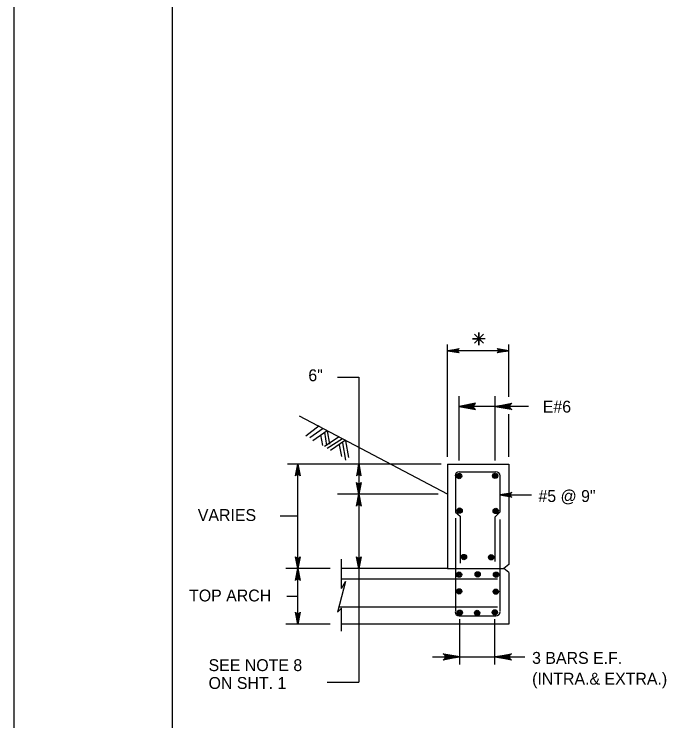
# Model space of a CAD drawing. Extents: x 639028 to 639883, y 298843 to 300031.
# Drawn here: x 639027.7 to 639195.5, y 299029.7 to 299207.9 of the extents above; entities that cross this region are included whole.
import ezdxf

# ---------------------------------------------------------------- set-up
doc = ezdxf.new("R2010")
doc.units = 0
for name, color, linetype in [('2', 7, 'Continuous'), ('52', 7, 'Continuous'), ('PLT-BNDY', 7, 'Continuous')]:
    doc.layers.add(name, color=color, linetype=linetype)

msp = doc.modelspace()

# ---------------------------------------------------------------- linework, layer by layer
at = {"layer": '2'}
for p, q in [((639067.74, 298858.08), (639067.74, 299422.08)), ((639145.06, 299126.04), (639145.06, 299126.04)), ((639137.11, 299096.29), (639137.11, 299124.56)), ((639152.61, 299111.37), (639152.61, 299124.56)), ((639152.61, 299123.03), (639137.11, 299123.03)), ((639109.36, 299116.33), (639114.74, 299116.33)), ((639114.74, 299116.33), (639114.74, 299094.45)), ((639140.04, 299095.33), (639140.04, 299111.56)), ((639149.16, 299095.33), (639149.16, 299111.56)), ((639157.6, 299108.97), (639140.04, 299108.97)), ((639137.11, 299086.83), (639099.74, 299106.53)), ((639152.61, 299096.29), (639152.61, 299107.03)), ((639104.74, 299104.08), (639101.36, 299101.45)), ((639105.74, 299103.45), (639102.36, 299101.08)), ((639106.74, 299102.83), (639103.11, 299100.33)), ((639106.11, 299102.45), (639106.61, 299099.08)), ((639106.74, 299102.83), (639107.36, 299099.45)), ((639105.11, 299101.83), (639105.61, 299099.08)), ((639109.74, 299101.33), (639106.11, 299098.83)), ((639110.61, 299100.83), (639106.74, 299098.33)), ((639111.36, 299100.45), (639107.61, 299097.83)), ((639109.74, 299099.33), (639110.36, 299096.33)), ((639110.61, 299099.83), (639111.36, 299095.45)), ((639111.36, 299100.33), (639112.11, 299096.08)), ((639135.56, 299094.45), (639096.76, 299094.45)), ((639099.36, 299068.08), (639099.36, 299094.45)), ((639114.74, 299094.45), (639114.74, 299086.83)), ((639137.11, 299094.45), (639152.61, 299094.45)), ((639137.11, 299094.45), (639137.11, 299068.08)), ((639152.61, 299094.45), (639152.61, 299069.08)), ((639140.11, 299092.45), (639149.36, 299092.45)), ((639139.11, 299091.45), (639139.11, 299082.33)), ((639150.36, 299091.45), (639150.36, 299082.33)), ((639134.74, 299086.83), (639109.36, 299086.83)), ((639114.74, 299086.83), (639114.74, 299039.39)), ((639099.36, 299081.33), (639094.86, 299081.33)), ((639139.11, 299082.33), (639140.36, 299081.33)), ((639140.36, 299081.33), (639140.36, 299069.45)), ((639150.36, 299082.33), (639149.11, 299081.08)), ((639149.11, 299081.08), (639149.11, 299069.83)), ((639139.11, 299080.83), (639139.11, 299057.33)), ((639150.36, 299080.45), (639150.36, 299057.33)), ((639110.36, 299063.08), (639110.36, 299070.45)), ((639152.61, 299069.08), (639151.36, 299068.08)), ((639107.52, 299068.08), (639096.36, 299068.08)), ((639099.36, 299054.08), (639099.36, 299068.08)), ((639137.11, 299068.08), (639110.36, 299068.08)), ((639137.11, 299068.08), (639151.36, 299068.08)), ((639152.61, 299067.08), (639151.36, 299068.08)), ((639152.61, 299067.08), (639152.61, 299054.08)), ((639149.74, 299065.45), (639110.36, 299065.45)), ((639099.36, 299061.07), (639096.56, 299061.07)), ((639149.74, 299058.33), (639109.61, 299058.33)), ((639110.36, 299052.33), (639110.36, 299058.08)), ((639149.36, 299056.08), (639140.11, 299056.08)), ((639140.22, 299043.9), (639140.22, 299055.28)), ((639149.07, 299043.9), (639149.07, 299055.28)), ((639107.52, 299054.08), (639096.36, 299054.08)), ((639152.61, 299054.08), (639110.36, 299054.08)), ((639133.31, 299045.79), (639156.66, 299045.79))]:
    msp.add_line(p, q, dxfattribs=at)
for points in [[(639146.66, 299126.04), (639143.46, 299126.04), (639145.06, 299126.04), (639145.06, 299124.44), (639145.06, 299127.64), (639145.06, 299126.04), (639146.19, 299127.17), (639143.93, 299124.91), (639145.06, 299126.04), (639146.19, 299124.91), (639143.93, 299127.17)], [(639110.36, 299063.08), (639111.36, 299064.83), (639109.36, 299057.08), (639110.36, 299058.08)], [(639140.22, 299045.79), (639136.03, 299045), (639136.19, 299045.11), (639136.35, 299045.22), (639136.43, 299045.36), (639136.52, 299045.51), (639136.54, 299045.65), (639136.56, 299045.79), (639136.54, 299045.93), (639136.52, 299046.07), (639136.43, 299046.21), (639136.35, 299046.35), (639136.19, 299046.46), (639136.03, 299046.57), (639140.22, 299045.79), (639136.19, 299046.46), (639136.35, 299046.35), (639140.22, 299045.79), (639136.43, 299046.21), (639136.52, 299046.07), (639140.22, 299045.79), (639136.54, 299045.93), (639136.56, 299045.79), (639140.22, 299045.79), (639136.54, 299045.65), (639136.52, 299045.51), (639140.22, 299045.79), (639136.43, 299045.36), (639136.35, 299045.22), (639140.22, 299045.79), (639136.19, 299045.11)], [(639149.07, 299045.79), (639153.26, 299046.57), (639153.1, 299046.46), (639152.94, 299046.35), (639152.86, 299046.21), (639152.77, 299046.07), (639152.75, 299045.93), (639152.73, 299045.79), (639152.75, 299045.65), (639152.77, 299045.51), (639152.86, 299045.36), (639152.94, 299045.22), (639153.1, 299045.11), (639153.26, 299045), (639149.07, 299045.79), (639153.1, 299045.11), (639152.94, 299045.22), (639149.07, 299045.79), (639152.86, 299045.36), (639152.77, 299045.51), (639149.07, 299045.79), (639152.75, 299045.65), (639152.73, 299045.79), (639149.07, 299045.79), (639152.75, 299045.93), (639152.77, 299046.07), (639149.07, 299045.79), (639152.86, 299046.21), (639152.94, 299046.35), (639149.07, 299045.79), (639153.1, 299046.46)]]:
    msp.add_lwpolyline(points, dxfattribs=at)
for centre, radius in [((639140.04, 299091.42), 0.668), ((639140.04, 299091.42), 0.527), ((639140.04, 299091.41), 0.37), ((639149.16, 299091.47), 0.668), ((639149.16, 299091.47), 0.527), ((639149.16, 299091.45), 0.37), ((639140.04, 299091.44), 0.202), ((639140.05, 299091.42), 0.0569), ((639149.16, 299091.48), 0.202), ((639149.18, 299091.47), 0.0569), ((639140.18, 299082.71), 0.668), ((639140.18, 299082.71), 0.527), ((639140.18, 299082.7), 0.37), ((639140.18, 299082.72), 0.202), ((639149.3, 299082.61), 0.668), ((639149.3, 299082.61), 0.527), ((639149.3, 299082.6), 0.37), ((639149.3, 299082.63), 0.202), ((639140.19, 299082.71), 0.0569), ((639149.31, 299082.61), 0.0569), ((639141.27, 299070.99), 0.668), ((639141.27, 299070.99), 0.527), ((639141.27, 299070.97), 0.37), ((639141.27, 299071), 0.202), ((639141.28, 299070.99), 0.0569), ((639148.15, 299070.94), 0.668), ((639148.15, 299070.94), 0.527), ((639148.15, 299070.93), 0.37), ((639148.15, 299070.96), 0.202), ((639148.17, 299070.94), 0.0569), ((639140.04, 299066.56), 0.668), ((639140.04, 299066.56), 0.527), ((639140.04, 299066.55), 0.37), ((639144.74, 299066.61), 0.668), ((639144.74, 299066.61), 0.527), ((639144.74, 299066.59), 0.37), ((639144.74, 299066.62), 0.202), ((639149.39, 299066.52), 0.668), ((639149.39, 299066.52), 0.527), ((639149.39, 299066.5), 0.37), ((639140.04, 299066.58), 0.202), ((639140.05, 299066.56), 0.0569), ((639144.75, 299066.61), 0.0569), ((639149.39, 299066.53), 0.202), ((639149.4, 299066.52), 0.0569), ((639140.06, 299062.33), 0.668), ((639140.06, 299062.33), 0.527), ((639140.06, 299062.32), 0.37), ((639140.06, 299062.34), 0.202), ((639140.07, 299062.33), 0.0569), ((639149.31, 299062.26), 0.668), ((639149.31, 299062.26), 0.527), ((639149.31, 299062.24), 0.37), ((639149.31, 299062.27), 0.202), ((639149.33, 299062.26), 0.0569), ((639140.22, 299056.94), 0.668), ((639140.22, 299056.94), 0.527), ((639140.22, 299056.92), 0.37), ((639140.22, 299056.95), 0.202), ((639140.24, 299056.94), 0.0569), ((639144.6, 299056.89), 0.668), ((639144.6, 299056.89), 0.527), ((639144.6, 299056.88), 0.37), ((639144.6, 299056.91), 0.202), ((639144.61, 299056.89), 0.0569), ((639149.07, 299057.03), 0.668), ((639149.07, 299057.03), 0.527), ((639149.07, 299057.02), 0.37), ((639149.07, 299057.05), 0.202), ((639149.08, 299057.03), 0.0569)]:
    msp.add_circle(centre, radius, dxfattribs=at)
for centre, start, end in [((639140.07, 299091.47), 90, 180), ((639149.35, 299091.47), 0, 90), ((639140.07, 299057.18), 180, 270), ((639149.35, 299057.18), 270, 0)]:
    msp.add_arc(centre, 1.03, start, end, dxfattribs=at)
at = {"layer": '52'}
for points in [[(639137.11, 299123.03), (639140.1, 299123.59), (639139.98, 299123.51), (639139.87, 299123.43), (639139.81, 299123.33), (639139.75, 299123.23), (639139.73, 299123.13), (639139.71, 299123.03), (639139.73, 299122.93), (639139.75, 299122.83), (639139.81, 299122.73), (639139.87, 299122.63), (639139.98, 299122.55), (639140.1, 299122.47), (639137.11, 299123.03), (639139.98, 299122.55), (639139.87, 299122.63), (639137.11, 299123.03), (639139.81, 299122.73), (639139.75, 299122.83), (639137.11, 299123.03), (639139.73, 299122.93), (639139.71, 299123.03), (639137.11, 299123.03), (639139.73, 299123.13), (639139.75, 299123.23), (639137.11, 299123.03), (639139.81, 299123.33), (639139.87, 299123.43), (639137.11, 299123.03), (639139.98, 299123.51)], [(639152.61, 299123.03), (639149.63, 299122.47), (639149.75, 299122.55), (639149.86, 299122.63), (639149.92, 299122.73), (639149.98, 299122.83), (639150, 299122.93), (639150.01, 299123.03), (639150, 299123.13), (639149.98, 299123.23), (639149.92, 299123.33), (639149.86, 299123.43), (639149.75, 299123.51), (639149.63, 299123.59), (639152.61, 299123.03), (639149.75, 299123.51), (639149.86, 299123.43), (639152.61, 299123.03), (639149.92, 299123.33), (639149.98, 299123.23), (639152.61, 299123.03), (639150, 299123.13), (639150.01, 299123.03), (639152.61, 299123.03), (639150, 299122.93), (639149.98, 299122.83), (639152.61, 299123.03), (639149.92, 299122.73), (639149.86, 299122.63), (639152.61, 299123.03), (639149.75, 299122.55)], [(639140.04, 299108.97), (639144.23, 299108.18), (639144.07, 299108.3), (639143.91, 299108.41), (639143.83, 299108.55), (639143.74, 299108.69), (639143.72, 299108.83), (639143.7, 299108.97), (639143.72, 299109.11), (639143.74, 299109.25), (639143.83, 299109.39), (639143.91, 299109.53), (639144.07, 299109.64), (639144.23, 299109.76), (639140.04, 299108.97), (639144.07, 299109.64), (639143.91, 299109.53), (639140.04, 299108.97), (639143.83, 299109.39), (639143.74, 299109.25), (639140.04, 299108.97), (639143.72, 299109.11), (639143.7, 299108.97), (639140.04, 299108.97), (639143.72, 299108.83), (639143.74, 299108.69), (639140.04, 299108.97), (639143.83, 299108.55), (639143.91, 299108.41), (639140.04, 299108.97), (639144.07, 299108.3)], [(639149.16, 299108.97), (639153.36, 299109.76), (639153.19, 299109.64), (639153.03, 299109.53), (639152.95, 299109.39), (639152.87, 299109.25), (639152.84, 299109.11), (639152.82, 299108.97), (639152.84, 299108.83), (639152.87, 299108.69), (639152.95, 299108.55), (639153.03, 299108.41), (639153.19, 299108.3), (639153.36, 299108.18), (639149.16, 299108.97), (639153.19, 299108.3), (639153.03, 299108.41), (639149.16, 299108.97), (639152.95, 299108.55), (639152.87, 299108.69), (639149.16, 299108.97), (639152.84, 299108.83), (639152.82, 299108.97), (639149.16, 299108.97), (639152.84, 299109.11), (639152.87, 299109.25), (639149.16, 299108.97), (639152.95, 299109.39), (639153.03, 299109.53), (639149.16, 299108.97), (639153.19, 299109.64)], [(639099.36, 299094.45), (639099.92, 299091.47), (639099.84, 299091.59), (639099.76, 299091.7), (639099.66, 299091.76), (639099.56, 299091.82), (639099.46, 299091.84), (639099.36, 299091.85), (639099.26, 299091.84), (639099.16, 299091.82), (639099.06, 299091.76), (639098.96, 299091.7), (639098.88, 299091.59), (639098.8, 299091.47), (639099.36, 299094.45), (639098.88, 299091.59), (639098.96, 299091.7), (639099.36, 299094.45), (639099.06, 299091.76), (639099.16, 299091.82), (639099.36, 299094.45), (639099.26, 299091.84), (639099.36, 299091.85), (639099.36, 299094.45), (639099.46, 299091.84), (639099.56, 299091.82), (639099.36, 299094.45), (639099.66, 299091.76), (639099.76, 299091.7), (639099.36, 299094.45), (639099.84, 299091.59)], [(639114.74, 299094.46), (639114.18, 299091.47), (639114.26, 299091.59), (639114.34, 299091.7), (639114.44, 299091.76), (639114.54, 299091.82), (639114.64, 299091.84), (639114.74, 299091.86), (639114.84, 299091.84), (639114.94, 299091.82), (639115.04, 299091.76), (639115.14, 299091.7), (639115.22, 299091.59), (639115.3, 299091.47), (639114.74, 299094.46), (639115.22, 299091.59), (639115.14, 299091.7), (639114.74, 299094.46), (639115.04, 299091.76), (639114.94, 299091.82), (639114.74, 299094.46), (639114.84, 299091.84), (639114.74, 299091.86), (639114.74, 299094.46), (639114.64, 299091.84), (639114.54, 299091.82), (639114.74, 299094.46), (639114.44, 299091.76), (639114.34, 299091.7), (639114.74, 299094.46), (639114.26, 299091.59)], [(639114.74, 299086.83), (639114.18, 299089.81), (639114.26, 299089.7), (639114.34, 299089.58), (639114.44, 299089.52), (639114.54, 299089.46), (639114.64, 299089.45), (639114.74, 299089.43), (639114.84, 299089.45), (639114.94, 299089.46), (639115.04, 299089.52), (639115.14, 299089.58), (639115.22, 299089.7), (639115.3, 299089.81), (639114.74, 299086.83), (639115.22, 299089.7), (639115.14, 299089.58), (639114.74, 299086.83), (639115.04, 299089.52), (639114.94, 299089.46), (639114.74, 299086.83), (639114.84, 299089.45), (639114.74, 299089.43), (639114.74, 299086.83), (639114.64, 299089.45), (639114.54, 299089.46), (639114.74, 299086.83), (639114.44, 299089.52), (639114.34, 299089.58), (639114.74, 299086.83), (639114.26, 299089.7)], [(639114.74, 299086.83), (639115.3, 299083.85), (639115.22, 299083.96), (639115.14, 299084.08), (639115.04, 299084.14), (639114.94, 299084.2), (639114.84, 299084.21), (639114.74, 299084.23), (639114.64, 299084.21), (639114.54, 299084.2), (639114.44, 299084.14), (639114.34, 299084.08), (639114.26, 299083.96), (639114.18, 299083.85), (639114.74, 299086.83), (639114.26, 299083.96), (639114.34, 299084.08), (639114.74, 299086.83), (639114.44, 299084.14), (639114.54, 299084.2), (639114.74, 299086.83), (639114.64, 299084.21), (639114.74, 299084.23), (639114.74, 299086.83), (639114.84, 299084.21), (639114.94, 299084.2), (639114.74, 299086.83), (639115.04, 299084.14), (639115.14, 299084.08), (639114.74, 299086.83), (639115.22, 299083.96)], [(639150.36, 299086.67), (639153.35, 299087.23), (639153.23, 299087.15), (639153.12, 299087.07), (639153.06, 299086.97), (639153, 299086.87), (639152.98, 299086.77), (639152.96, 299086.67), (639152.98, 299086.57), (639153, 299086.47), (639153.06, 299086.37), (639153.12, 299086.27), (639153.23, 299086.19), (639153.35, 299086.11), (639150.36, 299086.67), (639153.23, 299086.19), (639153.12, 299086.27), (639150.36, 299086.67), (639153.06, 299086.37), (639153, 299086.47), (639150.36, 299086.67), (639152.98, 299086.57), (639152.96, 299086.67), (639150.36, 299086.67), (639152.98, 299086.77), (639153, 299086.87), (639150.36, 299086.67), (639153.06, 299086.97), (639153.12, 299087.07), (639150.36, 299086.67), (639153.23, 299087.15)], [(639150.36, 299086.67), (639158.36, 299086.67)], [(639099.36, 299068.08), (639098.8, 299071.06), (639098.88, 299070.95), (639098.96, 299070.83), (639099.06, 299070.77), (639099.16, 299070.71), (639099.26, 299070.7), (639099.36, 299070.68), (639099.46, 299070.7), (639099.56, 299070.71), (639099.66, 299070.77), (639099.76, 299070.83), (639099.84, 299070.95), (639099.92, 299071.06), (639099.36, 299068.08), (639099.84, 299070.95), (639099.76, 299070.83), (639099.36, 299068.08), (639099.66, 299070.77), (639099.56, 299070.71), (639099.36, 299068.08), (639099.46, 299070.7), (639099.36, 299070.68), (639099.36, 299068.08), (639099.26, 299070.7), (639099.16, 299070.71), (639099.36, 299068.08), (639099.06, 299070.77), (639098.96, 299070.83), (639099.36, 299068.08), (639098.88, 299070.95)], [(639114.74, 299068.08), (639114.18, 299071.06), (639114.26, 299070.95), (639114.34, 299070.83), (639114.44, 299070.77), (639114.54, 299070.71), (639114.64, 299070.7), (639114.74, 299070.68), (639114.84, 299070.7), (639114.94, 299070.71), (639115.04, 299070.77), (639115.14, 299070.83), (639115.22, 299070.95), (639115.3, 299071.06), (639114.74, 299068.08), (639115.22, 299070.95), (639115.14, 299070.83), (639114.74, 299068.08), (639115.04, 299070.77), (639114.94, 299070.71), (639114.74, 299068.08), (639114.84, 299070.7), (639114.74, 299070.68), (639114.74, 299068.08), (639114.64, 299070.7), (639114.54, 299070.71), (639114.74, 299068.08), (639114.44, 299070.77), (639114.34, 299070.83), (639114.74, 299068.08), (639114.26, 299070.95)], [(639099.36, 299068.08), (639099.92, 299065.1), (639099.84, 299065.21), (639099.76, 299065.33), (639099.66, 299065.39), (639099.56, 299065.45), (639099.46, 299065.46), (639099.36, 299065.48), (639099.26, 299065.46), (639099.16, 299065.45), (639099.06, 299065.39), (639098.96, 299065.33), (639098.88, 299065.21), (639098.8, 299065.1), (639099.36, 299068.08), (639098.88, 299065.21), (639098.96, 299065.33), (639099.36, 299068.08), (639099.06, 299065.39), (639099.16, 299065.45), (639099.36, 299068.08), (639099.26, 299065.46), (639099.36, 299065.48), (639099.36, 299068.08), (639099.46, 299065.46), (639099.56, 299065.45), (639099.36, 299068.08), (639099.66, 299065.39), (639099.76, 299065.33), (639099.36, 299068.08), (639099.84, 299065.21)], [(639099.36, 299054.08), (639098.8, 299057.06), (639098.88, 299056.95), (639098.96, 299056.83), (639099.06, 299056.77), (639099.16, 299056.71), (639099.26, 299056.7), (639099.36, 299056.68), (639099.46, 299056.7), (639099.56, 299056.71), (639099.66, 299056.77), (639099.76, 299056.83), (639099.84, 299056.95), (639099.92, 299057.06), (639099.36, 299054.08), (639099.84, 299056.95), (639099.76, 299056.83), (639099.36, 299054.08), (639099.66, 299056.77), (639099.56, 299056.71), (639099.36, 299054.08), (639099.46, 299056.7), (639099.36, 299056.68), (639099.36, 299054.08), (639099.26, 299056.7), (639099.16, 299056.71), (639099.36, 299054.08), (639099.06, 299056.77), (639098.96, 299056.83), (639099.36, 299054.08), (639098.88, 299056.95)], [(639106.75, 299039.39), (639114.74, 299039.39)]]:
    msp.add_lwpolyline(points, dxfattribs=at)
at = {"layer": 'PLT-BNDY'}
msp.add_lwpolyline([(639027.74, 299437.08), (639868.74, 299437.08), (639868.74, 298843.08), (639027.74, 298843.08)], close=True, dxfattribs=at)

# ---------------------------------------------------------------- texts
at = {"layer": '2'}
for s, p in [('6"', (639102, 299115.33)), ('E#6', (639161.18, 299107.42)), ('#5 @ 9"', (639160.08, 299084.88)), (' VARIES ', (639072.99, 299080.08)), ('TOP ARCH', (639071.9, 299059.79)), ('3 BARS E.F.', (639158.48, 299044.05)), ('SEE NOTE 8', (639076.82, 299042.22)), ('(INTRA.& EXTRA.)', (639158.48, 299038.8)), ('ON SHT. 1', (639076.82, 299037.72))]:
    msp.add_text(s, height=3, dxfattribs=at).set_placement(p)

doc.saveas('drawing.dxf')
